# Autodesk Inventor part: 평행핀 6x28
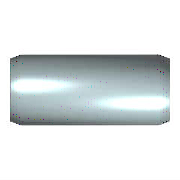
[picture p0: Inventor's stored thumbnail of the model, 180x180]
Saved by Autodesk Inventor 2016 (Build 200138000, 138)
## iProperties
Created: 2012-02
Part Number: 평행핀 6x28
Material: 스테인리스강
Description: 평행 핀
Document SubType Name: Modeling
Standard: KS B 1320
Designer: mduedu
Standards Organization: KS
Language: ko-KR
Size Designation: B 6 x  28
Categories: <MemberInstance><Categories><Category DisplayName="조임쇠" InternalName="e4da775c-781d-43d5-af7c-5136215cf5a6" Mnemonic="FSTN"><Category DisplayName="핀" InternalNa
Density: 1 g/cm^3
Appearance: 주황색
IsCustomPart: 1
Author: mduedu
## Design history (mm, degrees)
sketch "스케치"
  geometry: C1 r 3 at (0, 0); 1 further point
  constraints: 1 centre point, 1 coincident
  dimensions: "d1" = 6 diameter of C1 (= NND)
extrude "본체" new body sketch "스케치" distance "d2" = 28 (= NLG); taper "d3" = 0 deg
chamfer "스케치2" distance "d8" = 1.2 (= PHH); stored, may be unused: angle "d9" = 15 deg (= FAWI), second distance "d12" = 1.2 (= PHH)
node "작업 평면1"
body "Solid1"
chamfer "모따기1" distance "d4" = 1.2 (= PHH); stored, may be unused: angle "d5" = 15 deg (= FAWI), second distance "d11" = 1.2 (= PHH)
other parameters: "NND" = 6 [user parameter; used in 1 equation term], "NLG" = 28 [user parameter; used in 1 equation term], "PHH" = 1.2 [user parameter; used in 4 equation terms], "FAWI" = 15 deg [user parameter; used in 2 equation terms], "d13" = 0, "d15" = 0, "d16" = 0, "KAH" = 0.8 [user parameter]
